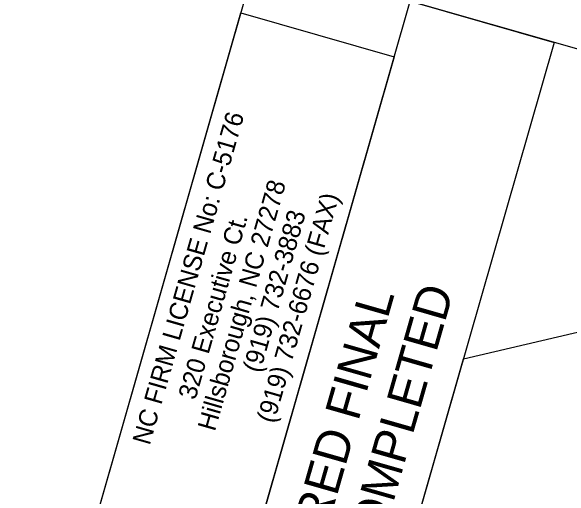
# Model space of a CAD drawing. Extents: x 2096990 to 2098506, y 687712 to 690186.
# Drawn here: x 2097612.2 to 2097704.1, y 689468.2 to 689548.2 of the extents above; entities that cross this region are included whole.
import ezdxf

# ---------------------------------------------------------------- set-up
doc = ezdxf.new("R2010")
doc.units = 0
for name, color, linetype in [('Sheet Block Title CELL', 7, 'Continuous'), ('Sheet Layout Plan Border', 7, 'Continuous'), ('Sheet Plan CELL', 7, 'Continuous'), ('Sheet Sticker Exception Certification CELL', 7, 'Continuous'), ('Sheet Title CELL', 7, 'Continuous')]:
    doc.layers.add(name, color=color, linetype=linetype)

msp = doc.modelspace()

# ---------------------------------------------------------------- linework, layer by layer
at = {"layer": 'Sheet Block Title CELL'}
msp.add_lwpolyline([(2097594.874, 689355.543), (2097649.931, 689547.876), (2097675.173, 689540.651), (2097620.116, 689348.318)], close=True, dxfattribs=at)
at = {"layer": 'Sheet Layout Plan Border'}
msp.add_lwpolyline([(2098367.95, 688928.374), (2098117.796, 688054.493), (2097561.265, 688075.837), (2097494.464, 688123.792), (2097678.883, 688820.989), (2097441.612, 689082.358), (2097412.963, 689407.616), (2097643.786, 689341.542), (2097686.552, 689490.939), (2097794.811, 689516.306), (2097855.092, 689499.05), (2097840.289, 689446.58), (2098381.232, 689292.721), (2098283.828, 688952.454)], close=True, dxfattribs=at)
at = {"layer": 'Sheet Plan CELL'}
msp.add_line((2098480.095, 689320.139), (2097470.639, 689609.102), dxfattribs=at)
at = {"layer": 'Sheet Sticker Exception Certification CELL'}
for p, q in [((2097620.116, 689348.318), (2097677.793, 689549.803)), ((2097677.805, 689549.799), (2097701.475, 689543.024)), ((2097701.463, 689543.027), (2097643.786, 689341.542))]:
    msp.add_line(p, q, dxfattribs=at)
at = {"layer": 'Sheet Title CELL'}
msp.add_line((2097652.55, 689557.029), (2097594.874, 689355.543), dxfattribs=at)

# ---------------------------------------------------------------- texts
at = {"layer": 'Sheet Block Title CELL'}
for s, p in [('NC FIRM LICENSE No: C-5176', (2097634.935, 689476.606)), ('Hillsborough, NC 27278', (2097645.662, 689478.89)), ('(919) 732-6676 (FAX)', (2097655.403, 689480.205)), ('(919) 732-3883', (2097653.097, 689488.507)), ('320 Executive Ct.', (2097642.459, 689484.058))]:
    msp.add_text(s, height=3.00087, rotation=74.02589, dxfattribs=at).set_placement(p)
at = {"layer": 'Sheet Sticker Exception Certification CELL'}
for s, p in [('UNLESS ALL SIGNATURES COMPLETED', (2097644.013, 689358.913)), ('DOCUMENT NOT CONSIDERED FINAL', (2097636.612, 689366.558))]:
    msp.add_text(s, height=5.76232, rotation=74.02589, dxfattribs=at).set_placement(p)

doc.saveas('drawing.dxf')
